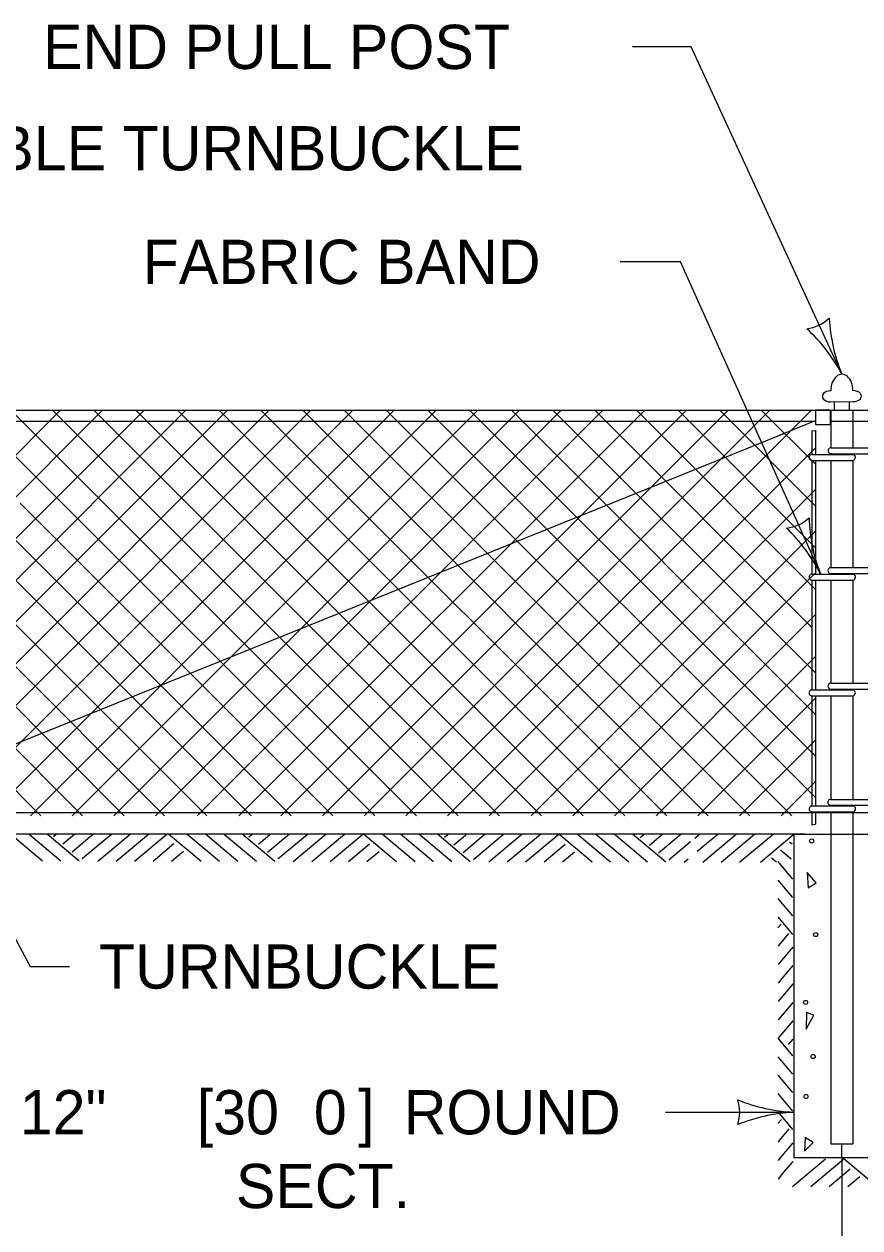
# Model space of a CAD drawing. Extents: x 49973.1 to 50021, y 49987.6 to 50015.4.
# Drawn here: x 49974.019 to 49975.152, y 50008.477 to 50010.109 of the extents above; entities that cross this region are included whole.
import ezdxf

# ---------------------------------------------------------------- set-up
doc = ezdxf.new("R2010")
doc.units = 0
for name, color, linetype in [('Level 1', 7, 'Continuous'), ('Level 2', 7, 'Continuous'), ('Level 3', 7, 'Continuous')]:
    doc.layers.add(name, color=color, linetype=linetype)

msp = doc.modelspace()

# ---------------------------------------------------------------- linework, layer by layer
at = {"layer": 'Level 1'}
for p, q in [((49973.7657, 50009.2828), (49974.0686, 50009.5857)), ((49973.7657, 50009.113), (49974.2384, 50009.5857)), ((49973.7657, 50009.2262), (49974.1252, 50009.5857)), ((49973.7657, 50009.1696), (49974.1818, 50009.5857)), ((49973.7657, 50009.0566), (49974.2948, 50009.5857)), ((49973.7769, 50009.5857), (49974.3269, 50009.0357)), ((49973.8311, 50009.5857), (49974.3811, 50009.0357)), ((49973.8378, 50009.0721), (49974.3514, 50009.5857)), ((49973.9146, 50009.0357), (49974.4646, 50009.5857)), ((49973.9263, 50009.5857), (49975.6696, 50009.5857)), ((49973.9377, 50009.1154), (49974.408, 50009.5857)), ((49973.9443, 50009.5857), (49974.0683, 50009.4618)), ((49973.971, 50009.0357), (49974.521, 50009.5857)), ((49974.0009, 50009.5857), (49974.5509, 50009.0357)), ((49974.0276, 50009.0357), (49974.5776, 50009.5857)), ((49974.0574, 50009.5857), (49974.6074, 50009.0357)), ((49974.0842, 50009.0357), (49974.6342, 50009.5857)), ((49974.1138, 50009.5857), (49974.6638, 50009.0357)), ((49974.1408, 50009.0357), (49974.6908, 50009.5857)), ((49974.1704, 50009.5857), (49974.7204, 50009.0357)), ((49974.7472, 50009.5857), (49974.1972, 50009.0357)), ((49974.2271, 50009.5857), (49974.7772, 50009.0357)), ((49974.8038, 50009.5857), (49974.2538, 50009.0357)), ((49974.2837, 50009.5857), (49974.8338, 50009.0357)), ((49974.8605, 50009.5857), (49974.3101, 50009.0357)), ((49974.3402, 50009.5857), (49974.8905, 50009.0357)), ((49974.917, 50009.5857), (49974.367, 50009.0357)), ((49974.3968, 50009.5857), (49974.9468, 50009.0357)), ((49974.9738, 50009.5857), (49974.4238, 50009.0357)), ((49974.4532, 50009.5857), (49975.0032, 50009.0357)), ((49975.0302, 50009.5857), (49974.4802, 50009.0357)), ((49974.51, 50009.5857), (49975.06, 50009.0357)), ((49975.0868, 50009.5857), (49974.5365, 50009.0357)), ((49974.5665, 50009.5857), (49975.0923, 50009.0603)), ((49974.6232, 50009.5857), (49975.0923, 50009.1166)), ((49974.6798, 50009.5857), (49975.0923, 50009.1732)), ((49975.0923, 50009.2295), (49974.7362, 50009.5857)), ((49975.0873, 50009.2911), (49974.7928, 50009.5857)), ((49975.0923, 50009.3427), (49974.8494, 50009.5857)), ((49975.0923, 50009.3991), (49974.906, 50009.5857)), ((49975.0923, 50009.4557), (49974.9624, 50009.5857)), ((49975.0922, 50009.5125), (49975.0184, 50009.5857)), ((49975.1129, 50009.5855), (49975.1129, 50009.5348)), ((49975.113, 50009.597), (49975.143, 50009.5973)), ((49975.118, 50009.5858), (49975.118, 50009.597)), ((49975.1381, 50009.5856), (49975.1381, 50009.5968)), ((49975.1429, 50009.5858), (49975.1429, 50009.5348)), ((49973.9265, 50009.5707), (49975.0922, 50009.5707)), ((49975.0432, 50009.5518), (49975.0922, 50009.5716)), ((49975.1128, 50009.5707), (49975.6696, 50009.5707)), ((49973.9511, 50009.1105), (49975.0483, 50009.5538)), ((49975.0873, 50009.5578), (49975.0923, 50009.5582)), ((49975.0873, 50009.5578), (49975.0873, 50009.5257)), ((49975.0923, 50009.5582), (49975.0923, 50009.5257)), ((49973.7657, 50009.5367), (49974.2667, 50009.0357)), ((49975.0923, 50009.5347), (49974.5932, 50009.0357)), ((49975.0874, 50009.5257), (49975.1436, 50009.5257)), ((49975.1132, 50009.5348), (49975.1694, 50009.5348)), ((49975.1132, 50009.5267), (49975.1692, 50009.5267)), ((49975.0873, 50009.5176), (49975.0873, 50009.3633)), ((49975.0874, 50009.5176), (49975.1434, 50009.5176)), ((49975.0923, 50009.5176), (49975.0923, 50009.3633)), ((49975.1129, 50009.5176), (49975.1129, 50009.3722)), ((49975.1429, 50009.5176), (49975.1429, 50009.3722)), ((49973.7657, 50009.4795), (49974.2095, 50009.0357)), ((49975.0923, 50009.4782), (49974.6498, 50009.0357)), ((49974.0138, 50009.4595), (49974.4379, 50009.0357)), ((49974.0682, 50009.4617), (49974.4945, 50009.0357)), ((49973.7657, 50009.425), (49974.1549, 50009.0357)), ((49975.0923, 50009.4215), (49974.7064, 50009.0357)), ((49973.7657, 50009.3684), (49974.0984, 50009.0357)), ((49975.0923, 50009.365), (49974.763, 50009.0357)), ((49975.0874, 50009.3633), (49975.1436, 50009.3633)), ((49975.113, 50009.3722), (49975.1692, 50009.3722)), ((49975.113, 50009.3641), (49975.169, 50009.3641)), ((49975.0873, 50009.3552), (49975.0873, 50009.2063)), ((49975.0874, 50009.3552), (49975.1434, 50009.3552)), ((49975.0923, 50009.3552), (49975.0923, 50009.2063)), ((49975.1129, 50009.3552), (49975.1129, 50009.2156)), ((49975.1429, 50009.3552), (49975.1429, 50009.2156)), ((49973.7657, 50009.3118), (49974.0419, 50009.0357)), ((49975.0923, 50009.3086), (49974.8194, 50009.0357)), ((49975.0923, 50009.2518), (49974.876, 50009.0357)), ((49975.113, 50009.2156), (49975.1692, 50009.2156)), ((49975.0923, 50009.1954), (49974.9326, 50009.0357)), ((49975.0872, 50009.2063), (49975.1434, 50009.2063)), ((49975.0872, 50009.1982), (49975.1432, 50009.1982)), ((49975.0873, 50009.1982), (49975.0873, 50009.049)), ((49975.0923, 50009.1982), (49975.0923, 50009.049)), ((49975.1129, 50009.1982), (49975.1129, 50009.058)), ((49975.113, 50009.2075), (49975.169, 50009.2075)), ((49975.1429, 50009.1982), (49975.1429, 50009.058)), ((49975.0923, 50009.1384), (49974.9892, 50009.0357)), ((49975.0923, 50009.0822), (49975.0458, 50009.0357)), ((49975.0875, 50009.049), (49975.1437, 50009.049)), ((49975.1126, 50009.058), (49975.1686, 50009.058)), ((49975.1126, 50009.0499), (49975.1686, 50009.0499)), ((49973.7232, 50009.0402), (49975.6696, 50009.0402)), ((49975.0873, 50009.0409), (49975.0873, 50009.0235)), ((49975.0875, 50009.0409), (49975.1435, 50009.0409)), ((49975.0923, 50009.0409), (49975.0923, 50009.0243)), ((49975.1129, 50009.0409), (49975.1129, 50008.5909)), ((49975.1429, 50009.0409), (49975.1429, 50008.5909)), ((49975.0873, 50009.0235), (49975.0923, 50009.0243)), ((49975.0779, 50009.0109), (49973.8032, 50009.0109)), ((49974.0439, 50008.9742), (49974.0004, 50009.0108)), ((49974.0259, 50009.0103), (49974.0254, 50009.0108)), ((49974.0689, 50008.9742), (49974.0259, 50009.0103)), ((49974.0939, 50008.9742), (49974.0504, 50009.0108)), ((49974.0589, 50009.0077), (49974.0626, 50009.0108)), ((49974.0716, 50008.9975), (49974.0873, 50009.0106)), ((49974.0841, 50008.987), (49974.1087, 50009.0076)), ((49974.0873, 50009.0106), (49974.0876, 50009.0108)), ((49974.098, 50008.9776), (49974.1303, 50009.0047)), ((49974.1087, 50009.0076), (49974.1126, 50009.0108)), ((49974.1189, 50008.9742), (49974.1627, 50009.0108)), ((49974.1303, 50009.0047), (49974.1377, 50009.0108)), ((49974.1439, 50008.9742), (49974.1877, 50009.0108)), ((49974.1689, 50008.9742), (49974.2126, 50009.0108)), ((49974.1939, 50008.9742), (49974.2223, 50008.998)), ((49974.259, 50008.9737), (49974.2149, 50009.0108)), ((49974.284, 50008.9737), (49974.2399, 50009.0108)), ((49974.309, 50008.9737), (49974.2649, 50009.0108)), ((49974.291, 50009.0098), (49974.2899, 50009.0108)), ((49974.334, 50008.9737), (49974.291, 50009.0098)), ((49974.359, 50008.9737), (49974.3149, 50009.0108)), ((49974.324, 50009.0072), (49974.3283, 50009.0108)), ((49974.3367, 50008.997), (49974.3524, 50009.0101)), ((49974.3492, 50008.9865), (49974.3738, 50009.0071)), ((49974.3524, 50009.0101), (49974.3533, 50009.0108)), ((49974.3631, 50008.9771), (49974.3954, 50009.0042)), ((49974.3738, 50009.0071), (49974.3783, 50009.0108)), ((49974.384, 50008.9737), (49974.4284, 50009.0108)), ((49974.3954, 50009.0042), (49974.4034, 50009.0108)), ((49974.409, 50008.9737), (49974.4534, 50009.0108)), ((49974.434, 50008.9737), (49974.4783, 50009.0108)), ((49974.459, 50008.9737), (49974.4874, 50008.9975)), ((49974.5241, 50008.9732), (49974.4794, 50009.0108)), ((49974.5491, 50008.9732), (49974.5044, 50009.0108)), ((49974.5741, 50008.9732), (49974.5294, 50009.0108)), ((49974.5561, 50009.0093), (49974.5544, 50009.0108)), ((49974.5991, 50008.9732), (49974.5561, 50009.0093)), ((49974.6241, 50008.9732), (49974.5794, 50009.0108)), ((49974.5891, 50009.0067), (49974.5941, 50009.0109)), ((49974.6018, 50008.9965), (49974.6175, 50009.0096)), ((49974.6143, 50008.986), (49974.6389, 50009.0066)), ((49974.6175, 50009.0096), (49974.619, 50009.0108)), ((49974.6282, 50008.9766), (49974.6605, 50009.0037)), ((49974.6389, 50009.0066), (49974.644, 50009.0108)), ((49974.6491, 50008.9732), (49974.6941, 50009.0108)), ((49974.6605, 50009.0037), (49974.6691, 50009.0108)), ((49974.6741, 50008.9732), (49974.7191, 50009.0108)), ((49974.6991, 50008.9732), (49974.7439, 50009.0108)), ((49974.7892, 50008.9727), (49974.7439, 50009.0108)), ((49974.8142, 50008.9727), (49974.7689, 50009.0108)), ((49974.8392, 50008.9727), (49974.7939, 50009.0108)), ((49974.8212, 50009.0088), (49974.8189, 50009.0108)), ((49974.8642, 50008.9727), (49974.8212, 50009.0088)), ((49974.8892, 50008.9727), (49974.8439, 50009.0108)), ((49974.8542, 50009.0062), (49974.8592, 50009.0104)), ((49974.8592, 50009.0104), (49974.8597, 50009.0108)), ((49974.8669, 50008.996), (49974.8826, 50009.0091)), ((49974.8794, 50008.9855), (49974.904, 50009.0061)), ((49974.8826, 50009.0091), (49974.8847, 50009.0108)), ((49974.8933, 50008.9761), (49974.9225, 50009.0007)), ((49974.904, 50009.0061), (49974.9097, 50009.0108)), ((49974.9283, 50009.0055), (49974.9348, 50009.0108)), ((49974.9319, 50008.9876), (49974.9597, 50009.0108)), ((49974.9392, 50008.9727), (49974.9847, 50009.0108)), ((49974.9642, 50008.9727), (49975.0096, 50009.0108)), ((49974.9892, 50008.9727), (49975.0347, 50009.0108)), ((49975.0174, 50008.9728), (49975.0629, 50009.0109)), ((49975.0603, 50008.997), (49975.0568, 50008.9999)), ((49975.0629, 50009.0109), (49975.0629, 50008.5718)), ((49975.0629, 50009.0109), (49975.1929, 50009.0109)), ((49974.2189, 50008.9742), (49974.2352, 50008.9879)), ((49974.484, 50008.9737), (49974.5003, 50008.9874)), ((49974.7241, 50008.9732), (49974.7525, 50008.997)), ((49974.7491, 50008.9732), (49974.7654, 50008.9869)), ((49975.0591, 50008.977), (49975.0447, 50008.989)), ((49974.9142, 50008.9727), (49974.9195, 50008.9772)), ((49975.0392, 50008.9727), (49975.0324, 50008.9784)), ((49975.0612, 50008.9498), (49975.0413, 50008.9735)), ((49975.0612, 50008.9248), (49975.0413, 50008.9485)), ((49975.0428, 50008.9218), (49975.0413, 50008.9235)), ((49975.0612, 50008.8998), (49975.0428, 50008.9218)), ((49975.0454, 50008.8888), (49975.0412, 50008.8838)), ((49975.0612, 50008.8748), (49975.0413, 50008.8985)), ((49975.0556, 50008.8761), (49975.0425, 50008.8604)), ((49975.0425, 50008.8604), (49975.0413, 50008.8589)), ((49975.0612, 50008.8577), (49975.0455, 50008.839)), ((49975.0455, 50008.839), (49975.0413, 50008.8339)), ((49975.0612, 50008.8326), (49975.0484, 50008.8174)), ((49975.0484, 50008.8174), (49975.0413, 50008.8088)), ((49975.0612, 50008.8076), (49975.0413, 50008.7838)), ((49975.0612, 50008.7826), (49975.0413, 50008.7588)), ((49975.0612, 50008.7577), (49975.0413, 50008.734)), ((49975.0612, 50008.7103), (49975.0413, 50008.734)), ((49975.0612, 50008.7326), (49975.0551, 50008.7254)), ((49975.0612, 50008.6853), (49975.0413, 50008.709)), ((49975.0612, 50008.6603), (49975.0413, 50008.684)), ((49975.0433, 50008.6567), (49975.0413, 50008.659)), ((49975.0612, 50008.6353), (49975.0433, 50008.6567)), ((49975.0612, 50008.6103), (49975.0413, 50008.634)), ((49975.0459, 50008.6237), (49975.0417, 50008.6187)), ((49975.0417, 50008.6187), (49975.0413, 50008.6182)), ((49975.0561, 50008.611), (49975.043, 50008.5953)), ((49975.043, 50008.5953), (49975.0413, 50008.5932)), ((49975.0612, 50008.592), (49975.046, 50008.5739)), ((49975.1129, 50008.5909), (49975.1429, 50008.5909)), ((49975.1279, 50008.5909), (49975.1279, 50008.5903)), ((49975.046, 50008.5739), (49975.0413, 50008.5682)), ((49975.0612, 50008.5669), (49975.0489, 50008.5523)), ((49975.0608, 50008.533), (49975.1058, 50008.5706)), ((49975.1929, 50008.5718), (49975.0629, 50008.5718)), ((49975.0858, 50008.533), (49975.1306, 50008.5706)), ((49975.1108, 50008.533), (49975.1392, 50008.5568)), ((49975.1759, 50008.5325), (49975.1306, 50008.5706)), ((49975.0489, 50008.5523), (49975.0413, 50008.5431)), ((49975.1358, 50008.533), (49975.1521, 50008.5467))]:
    msp.add_line(p, q, dxfattribs=at)
for points in [[(49975.1125, 50009.5661), (49975.1125, 50009.5857), (49975.0922, 50009.5857), (49975.0922, 50009.5661)], [(49975.0931, 50008.9446), (49975.0807, 50008.959), (49975.0821, 50008.9378)], [(49975.0897, 50008.7655), (49975.0801, 50008.769), (49975.0794, 50008.7463)], [(49975.089, 50008.5926), (49975.078, 50008.5995), (49975.0773, 50008.581)]]:
    msp.add_lwpolyline(points, close=True, dxfattribs=at)
for centre in [(49975.0869, 50009.0015), (49975.0924, 50008.8746), (49975.0787, 50008.7826), (49975.0889, 50008.7092), (49975.0793, 50008.655)]:
    msp.add_circle(centre, 0.00279, dxfattribs=at)
for centre, radius, start, end in [((49975.0875, 50009.5217), 0.00405, 87.9212, 274.9002), ((49975.1133, 50009.5308), 0.00405, 87.9212, 274.9002), ((49975.1422, 50009.5218), 0.00417, 282.5816, 72.0167), ((49975.0875, 50009.3593), 0.00405, 87.9212, 274.9002), ((49975.1131, 50009.3682), 0.00405, 87.9212, 274.9002), ((49975.1422, 50009.3594), 0.00417, 282.5816, 72.0167), ((49975.1131, 50009.2116), 0.00405, 87.9212, 274.9002), ((49975.0873, 50009.2023), 0.00405, 87.9212, 274.9002), ((49975.142, 50009.2024), 0.00417, 282.5816, 72.0167), ((49975.0876, 50009.045), 0.00405, 87.9212, 274.9002), ((49975.1127, 50009.054), 0.00405, 87.9212, 274.9002), ((49975.1423, 50009.0451), 0.00417, 282.5816, 72.0167)]:
    msp.add_arc(centre, radius, start, end, dxfattribs=at)
for centre, major_axis, ratio, start_param, end_param in [((49975.1279, 50009.6119), (0, -0.0226), 0.66398, 1.570796, 4.712389), ((49975.1129, 50009.6045), (0.0115, 0.0001), 0.649749, 1.570796, 4.712389), ((49975.143, 50009.6048), (0.0115, -0.0001), 0.649749, 4.712389, 7.853982)]:
    msp.add_ellipse(centre, major_axis=major_axis, ratio=ratio, start_param=start_param, end_param=end_param, dxfattribs=at)
at = {"layer": 'Level 3'}
for p, q in [((49974.9237, 50010.0784), (49974.8441, 50010.0784)), ((49975.1279, 50009.6345), (49974.9237, 50010.0784)), ((49974.909, 50009.7869), (49974.8273, 50009.7869)), ((49975.0992, 50009.3633), (49974.909, 50009.7869)), ((49973.894, 50009.0802), (49974.0272, 50008.8313)), ((49974.0272, 50008.8313), (49974.0806, 50008.8313)), ((49974.8889, 50008.6337), (49975.0629, 50008.6337)), ((49975.1279, 50008.5718), (49975.1279, 50008.5903)), ((49975.1279, 50008.5718), (49975.1279, 50008.2315))]:
    msp.add_line(p, q, dxfattribs=at)
for centre, radius, start, end in [((49975.0732, 50009.7505), 0.0548, 277.3534, 313.0758), ((49975.3433, 50009.7233), 0.233, 183.1374, 202.3873), ((49974.9308, 50009.5316), 0.2223, 27.5751, 47.7586), ((49975.0468, 50009.4804), 0.0548, 276.2488, 311.9712), ((49975.3056, 50009.4457), 0.2223, 181.566, 201.7495), ((49974.8914, 50009.2578), 0.233, 26.9373, 46.1872), ((49975.072, 50008.8559), 0.2223, 247.456, 267.6395), ((49974.9346, 50008.6337), 0.0548, 342.1388, 17.8612), ((49975.0743, 50008.401), 0.233, 92.8273, 112.0772)]:
    msp.add_arc(centre, radius, start, end, dxfattribs=at)

# ---------------------------------------------------------------- texts
at = {"layer": 'Level 2'}
for s, p in [('END PULL POST', (49974.0448, 50010.0484)), ('FABRIC BAND', (49974.1799, 50009.7569)), ('TURNBUCKLE', (49974.1206, 50008.8013)), ('12" ', (49974.0131, 50008.6037)), ('[30', (49974.2531, 50008.6037)), ('0', (49974.4119, 50008.6037)), (']', (49974.4719, 50008.6037)), (' ROUND', (49974.5115, 50008.6037)), ('SECT.', (49974.3062, 50008.5037))]:
    msp.add_text(s, height=0.06, dxfattribs=at).set_placement(p)
msp.add_text('CABLE TURNBUCKLE', height=0.06, rotation=360, dxfattribs=at).set_placement((49973.8672, 50009.9109))

doc.saveas('drawing.dxf')
